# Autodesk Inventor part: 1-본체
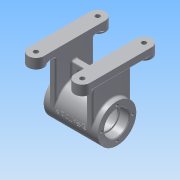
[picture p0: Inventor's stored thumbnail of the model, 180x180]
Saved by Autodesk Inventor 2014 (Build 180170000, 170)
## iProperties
Created: 2015-11
Part Number: 1-본체
Material: 알루미늄 6061
Document SubType Name: Modeling
Designer: 103-19
Density: 2.71 g/cm^3
Appearance: 알루미늄 - 평지
Mass: 357.834 g
Surface Area: 460.865 cm^2
Volume: 132.042 cm^3
Author: 103-19
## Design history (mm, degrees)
sketch "스케치1"
  geometry: L1 (0, 0)-(-70, 0); L2 (0, 0)-(0, 25); L3 (0, 25)-(-70, 25); L4 (-70, 25)-(-70, 0)
  constraints: 8 end point, 2 perpendicular, 1 horizontal, 1 parallel
  dimensions: "d0" = 70 distance of L1.start L1.end; "d1" = 50 diameter of L3 L1
revolve "회전1" sketch "스케치1" stored, may be unused: angle "d2" = 90 deg
node "작업 평면1"
sketch "스케치2"
  geometry: L1 (-5, 50)-(15, 50); L2 (15, 50)-(15, -50); L3 (15, -50)-(-5, -50); L4 (-5, -50)-(-5, 50); L5 (-5, 50)-(15, -50); L6 (15, 50)-(-5, -50); L7 (55, 50)-(75, 50); L8 (75, 50)-(75, -50); L9 (75, -50)-(55, -50); L10 (55, -50)-(55, 50); L11 (55, 50)-(75, -50); L12 (75, 50)-(55, -50); L13 (70, 25)-(0, 25) reference; L14 (35, 25)-(35, -25); L15 (0, 0)-(75, 0); L16 (0, 25)-(0, -25) reference; L17 (70, 25)-(70, -25) reference; L18 (70, -25)-(0, -25) reference; 2 further points
  constraints: 28 end point, 7 midpoint, 4 parallel, 4 perpendicular, 2 equal length, 2 horizontal, 1 collinear
  dimensions: "d4" = 20 distance of L1.start L1.end; "d7" = 80 distance between parallel lines of L8 L4; "d8" = 40 distance between parallel lines of L14 L4; "d9" = 100 distance of L3.end L1.start; "d10" = 50 distance between parallel lines of L15 L1
extrude "돌출1" join sketch "스케치2" distance "d11" = 10; taper "d12" = 0 deg
fillet "모깎기1" dims "d13" = 10
sketch "스케치3"
  geometry: L1 (55, -40)-(55, 40) reference; L2 (75, 40)-(75, -40) reference; C1 r 10 at (5, 40); C2 r 10 at (65, 40); C3 r 10 at (65, -40); C4 r 10 at (5, -40); A1 r 10 centre (5, -40) between (-5, -40) and (15, -40) reference; A2 r 10 centre (5, 40) between (15, 40) and (-5, 40) reference; A3 r 10 centre (65, -40) between (55, -40) and (75, -40) reference; A4 r 10 centre (65, 40) between (75, 40) and (55, 40) reference; 1 further point
  constraints: 4 centre point, 4 coincident, 4 concentric
extrude "돌출2" join sketch "스케치3" distance "d14" = 3; taper "d15" = 0 deg
sketch "스케치4"
  geometry: L1 (-10, 0)-(-10, 80) reference; L2 (-68, 15)-(-10, 15); L3 (-68, 65)-(-10, 65); A1 r 25 centre (-68, 40) between (-68, 15) and (-68, 65) reference; 1 further point
  constraints: 4 end point, 2 perpendicular, 2 point on circle, 2 point on line, 2 tangent
extrude "돌출3" join sketch "스케치4" distance "d16" = 8; taper "d17" = 0 deg
node "작업 평면2"
hole "구멍1" diameter "d20" = 28; stored, may be unused: countersink angle "d24" = 90 deg, drill point angle "d26" = 0 deg; dims "d18" = 10, "d19" = 10, "d21" = 6, "d22" = 32, "d23" = 12, "d25" = 14
hole "구멍2" diameter "d29" = 42; stored, may be unused: countersink angle "d33" = 90 deg, drill point angle "d35" = 0 deg; dims "d27" = 10, "d28" = 10, "d30" = 6, "d31" = 32, "d32" = 12, "d34" = 42
sketch "스케치5" dims "d36" = 40
  geometry: C1 r 16 at (0, 0) reference; C2 r 25 at (0, 0) reference; 5 further points
  constraints: 2 vertical alignment, 1 coincident, 7 other
  dimensions: "d39" = 360 deg dimension on C1.centre point (0, 20) (derived)
hole "구멍3" sketch "스케치5" at (0, 20), (-20, 0), (0, -20), (20, 0) diameter "d41" = 3.242; stored, may be unused: countersink angle "d45" = 90 deg, drill point angle "d47" = 118 deg; dims "d42" = 8, "d43" = 32, "d44" = 12, "d46" = 10
node "작업 평면3"
sketch "스케치6"
  geometry: L1 (55, 0)-(55, 58) reference; L2 (15, 0)-(15, 58) reference; L3 (55, 12)-(15, 12); L4 (55, 45)-(15, 45); L5 (70, 25)-(0, 25) reference; 1 further point
  constraints: 4 end point, 4 point on line, 2 perpendicular
  dimensions: "d82" = 20 distance between parallel lines of L4 L5; "d83" = 33 distance between parallel lines of L4 L3
extrude "돌출4" join sketch "스케치6" stored distance "d53" = 8; taper "d54" = 0 deg
sketch "스케치8"
  geometry: C1 r 10 at (0, 0) reference; C2 r 10 at (0, 80) reference; C3 r 10 at (60, 80) reference; C4 r 10 at (60, 0) reference; 5 further points
  constraints: 4 coincident
hole "구멍4" sketch "스케치8" at (0, 80), (60, 80), (60, 0), (0, 0) diameter "d60" = 6; stored, may be unused: countersink angle "d64" = 90 deg, drill point angle "d66" = 0 deg; dims "d61" = 8, "d62" = 12, "d63" = 4, "d65" = 4
chamfer "모따기1" distance "d67" = 1; stored, may be unused: second distance "d68" = 2, angle "d69" = 45 deg
fillet "모깎기2" dims "d70" = 0.3
fillet "모깎기3" dims "d71" = 2
fillet "모깎기4" dims "d72" = 2
fillet "모깎기5" dims "d73" = 2
fillet "모깎기6" dims "d74" = 2
node "작업 평면4"
sketch "스케치9"
  geometry: L1 (-35, -25)-(35, -25) reference; 2 further points
  constraints: 1 other
  dimensions: "d75" = 35 distance of point (0, 0) point (35, 0); "d76" = 25 distance from line of point (0, 0) L1
feature "엠보싱1" sketch "스케치9" dims "d77" = 0.5, "d78" = 0
node "작업 평면5"
sketch "스케치10"
  geometry: C1 r 14 at (0, 0) reference; C2 r 21 at (0, 0) reference; 1 further point
extrude "돌출6" cut sketch "스케치10" stored distance "d84" = 42; taper "d85" = 0 deg
sketch "스케치11"
  geometry: L1 (-55, 24.678)-(-55, 45) reference; L2 (-43, 38.5)-(-27, 38.5); L3 (-27, 31.5)-(-43, 31.5); L4 (-70, -25)-(0, -25) reference; L5 (0, -25)-(0, 25) reference; L6 (-75, 68)-(-55, 68) reference; A1 r 3.5 centre (-27, 35) between (-27, 31.5) and (-27, 38.5); A2 r 3.5 centre (-43, 35) between (-43, 38.5) and (-43, 31.5); 3 further points
  constraints: 4 end point, 4 point on circle, 4 tangent, 2 centre point, 2 midpoint, 1 parallel, 1 perpendicular, 1 vertical alignment
  dimensions: "d86" = 23 dimension on A1 A2; "d87" = 7 distance between parallel lines of L3 L2; "d88" = 33 distance from line of A2.centre L6
extrude "돌출7" cut sketch "스케치11" stored distance "d89" = 42; taper "d90" = 0 deg
fillet "모깎기10" dims "d91" = 2
fillet "모깎기11" dims "d92" = 2
fillet "모깎기12" dims "d93" = 2
fillet "모깎기13" dims "d94" = 3
fillet "모깎기14" dims "d95" = 0.3
chamfer "모따기2" distance "d96" = 1; stored, may be unused: second distance "d97" = 2, angle "d98" = 45 deg
node "작업 평면7"
sketch "스케치12"
  geometry: L1 (70, 25)-(0, 25) reference; L2 (70, 25)-(70, -25) reference; C1 r 5 at (35, 0); 1 further point
  constraints: 1 centre point, 1 horizontal alignment
  dimensions: "d100" = 35 distance from line of C1.centre L2; "d101" = 10 diameter of C1
extrude "돌출8" join sketch "스케치12" stored distance "d102" = 42; taper "d103" = 0 deg
hole "구멍5" diameter "d106" = 5.188; stored, may be unused: countersink angle "d110" = 90 deg, drill point angle "d112" = 0 deg; dims "d107" = 8, "d108" = 12, "d109" = 4, "d111" = 4, "d132" = 10, "d133" = 10
node "작업 평면8"
sketch "스케치13"
  geometry: L1 (0, 0)-(14, 24.249); 2 further points
  constraints: 2 end point, 2 vertical alignment, 1 other
  dimensions: "d114" = 28 distance of L1.start L1.end; "d115" = 30 deg dimension on point (0, 0) L1.end point (0, 14)
node "작업 평면9"
sketch "스케치14"
  geometry: C1 r 6 at (0, 0); 2 further points
  constraints: 1 centre point, 1 coincident
  dimensions: "d116" = 12 diameter of C1
extrude "돌출9" join sketch "스케치14" stored distance "d117" = 42; taper "d118" = 0 deg
hole "구멍6" diameter "d121" = 5.188; stored, may be unused: countersink angle "d125" = 90 deg, drill point angle "d127" = 0 deg; dims "d122" = 8, "d123" = 12, "d124" = 4, "d126" = 4, "d130" = 10, "d131" = 10
fillet "모깎기15" dims "d128" = 2
fillet "모깎기16" dims "d129" = 2
node "솔리드1"
mirror "대칭1"
mirror "대칭2"
mirror "대칭3"
node "투영된 루프1"
node "투영된 루프2"
node "투영된 루프3"
node "투영된 루프4"
node "투영된 루프5"
node "투영된 루프6"
other parameters: "d3" = 68, "d48" = 0, "d99" = -28, "d113" = -35
